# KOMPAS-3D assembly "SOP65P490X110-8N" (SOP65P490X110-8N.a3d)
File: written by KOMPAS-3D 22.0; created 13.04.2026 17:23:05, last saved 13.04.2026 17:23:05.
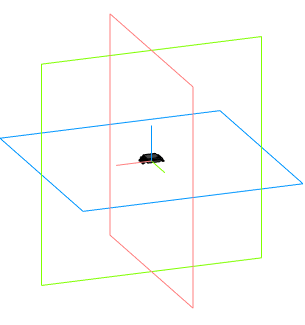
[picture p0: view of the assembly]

Document properties: Автор: Andrey; Полное имя файла: C:\Users\User1\Documents\SOP65P490X110-8N.a3d

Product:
- Component [detail]: HYM8563TS  | qty 1  | source file: HYM8563TS.m3d
- Part/product: SOP65P490X110-8N
    Комментарий: SOP65P490X110-8N

Expressions: SOP65P490X110-8N
Referenced files in C:\Users\User1\Documents\: HYM8563TS.m3d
